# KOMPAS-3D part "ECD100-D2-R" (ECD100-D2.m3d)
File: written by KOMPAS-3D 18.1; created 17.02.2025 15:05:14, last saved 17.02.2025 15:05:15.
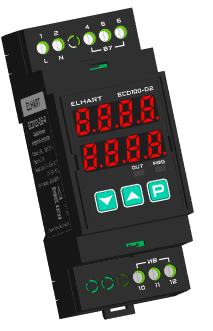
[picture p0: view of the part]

Document properties: Полное имя файла: Z:\Элхарт\БД\3D модели\ЭЛХАРТ\ECD100-D2-R\ECD100-D2.m3d

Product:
- Part/product: ECD100-D2-R

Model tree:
1. Операция без истории:1
2. Операция без истории:2
3. Операция без истории:3
4. Операция без истории:4
5. Операция без истории:5
6. Операция без истории:6
7. Операция без истории:7
8. Операция без истории:8
9. Операция без истории:9
10. Операция без истории:10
